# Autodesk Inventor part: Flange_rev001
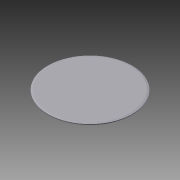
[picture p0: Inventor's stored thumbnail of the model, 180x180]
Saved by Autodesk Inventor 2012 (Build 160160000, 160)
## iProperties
Created: 2011-12
Part Number: Flange_rev001
Document SubType Name: Modeling
Designer: Alex
Density: 2.71 g/cm^3
Material: Aluminum-6061
Mass: 34.2083 g
Surface Area: 165.938 cm^2
Volume: 12.623 cm^3
Author: Alex
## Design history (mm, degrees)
sketch "Sketch1"
  geometry: L1 (0, 0)-(48.768, 0); L2 (48.768, 0)-(50.864, -0.601); L3 (0, -1.578)-(0, 0); L4 (50.864, -0.601)-(50.864, -1.578); L5 (0, -1.893)-(0, 0.316) reference; L6 (50.864, -1.578)-(0, -1.578); 1 further point
  constraints: 10 end point, 3 perpendicular, 2 point on line, 1 horizontal
  dimensions: "d1" = 48.768 distance of L1.end point (0, 0); "d2" = 164 deg angle of L2 L1; "d11" = 0.60087 vertical distance of L2.end L1.end (derived); "d12" = 1.57752 distance between parallel lines of L6 L1; "d13" = 2.0955 horizontal distance of L2.end L1.end; "d14" = 0.97664 distance of L4.end L2.end (derived); "d15" = 50.8635 distance from line of L4.end L3 (derived)
revolve "Revolution1" sketch "Sketch1" stored, may be unused: angle "d8" = 90 deg
body "Solid1"
